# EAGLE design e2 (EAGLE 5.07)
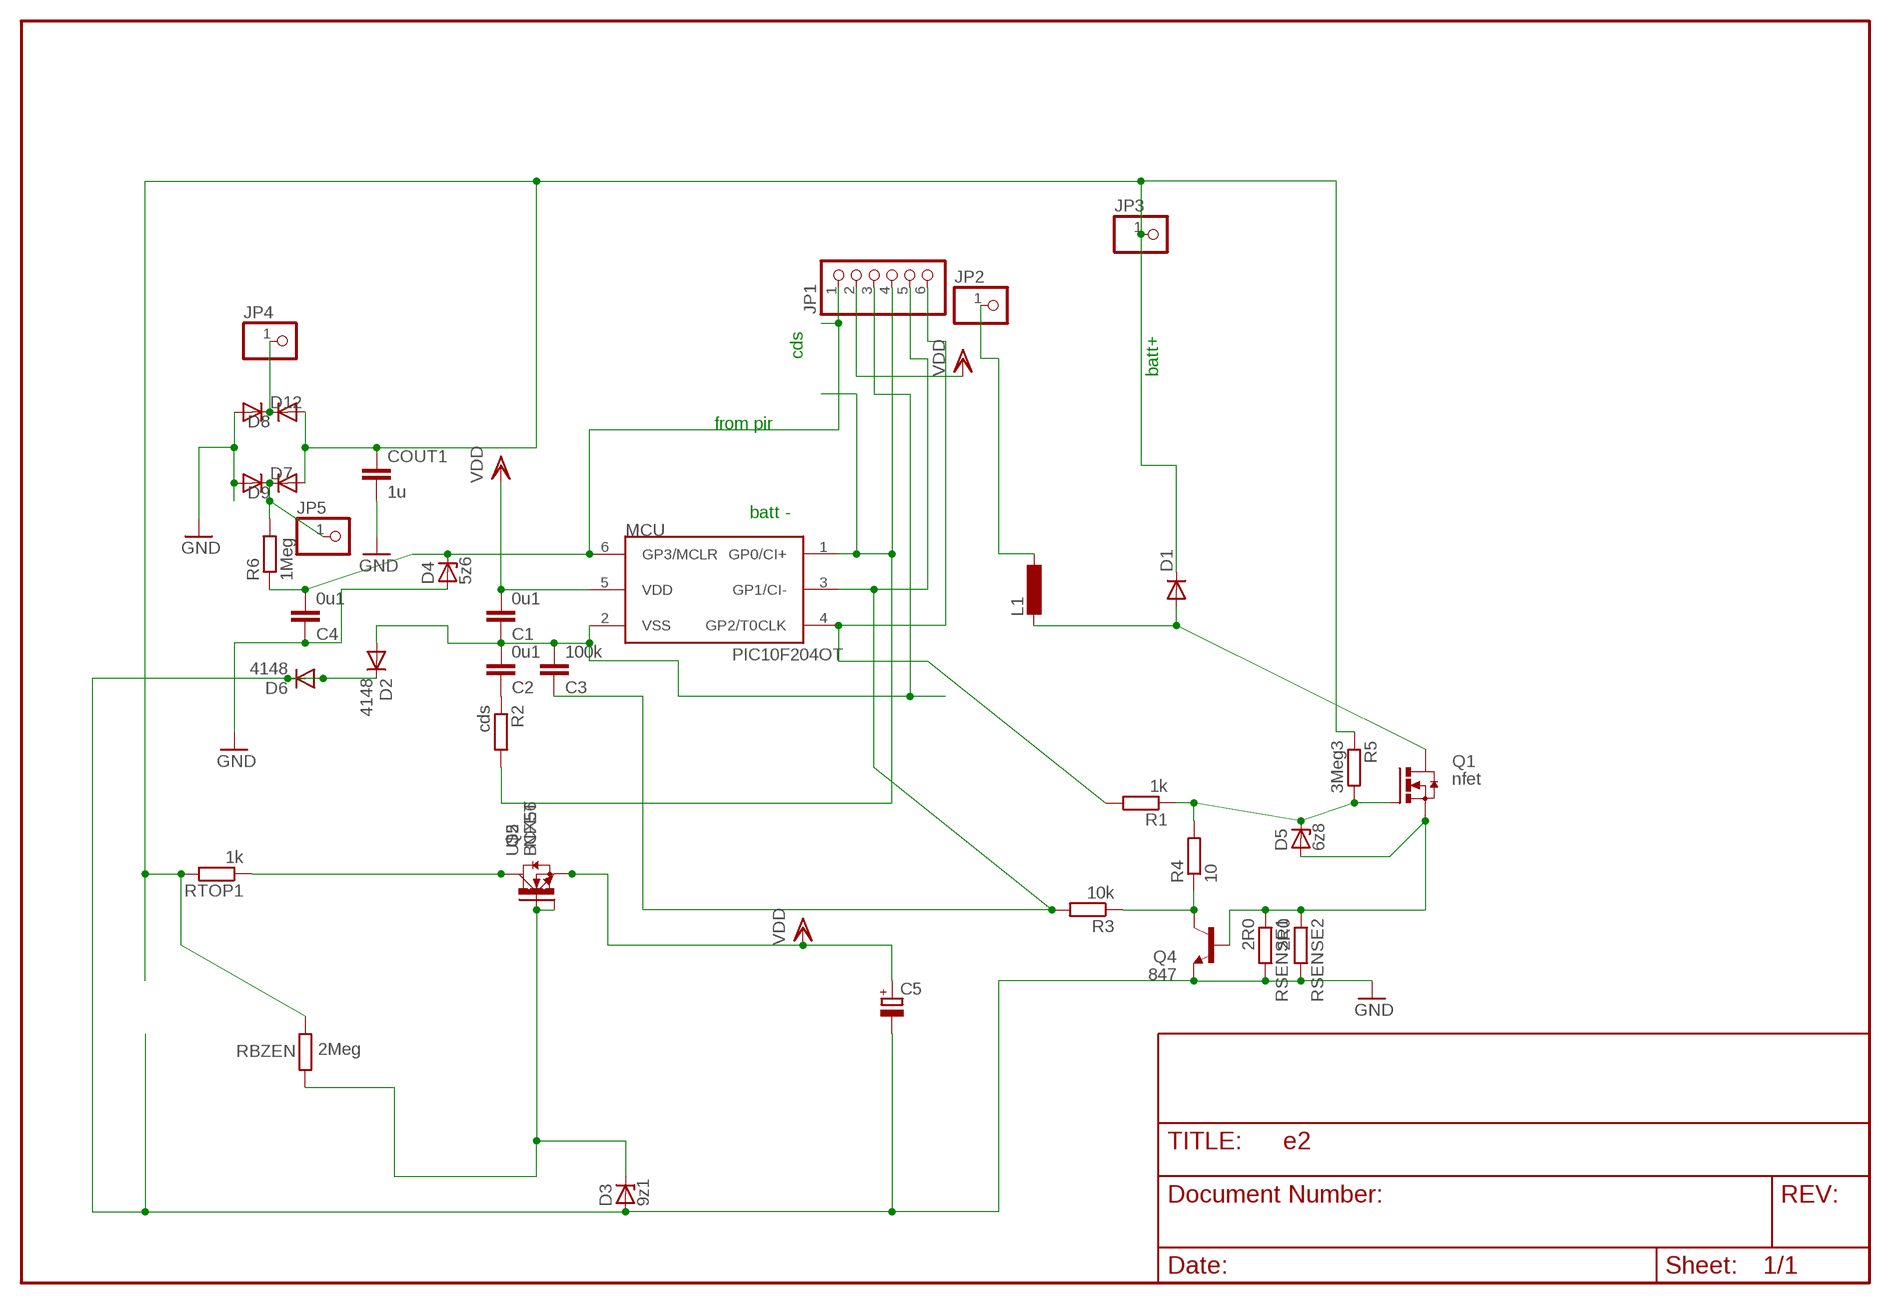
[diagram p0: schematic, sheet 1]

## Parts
C1  0u1  C-EUC1206  [C1206]
C2  0u1  C-EUC0805  [C0805]
C3  100k  C-EUC1206  [C1206]
C4  0u1  C-EUC1206  [C1206]
C5  CPOL-EUSANYO_SMD_C6  [SANYO-OSCON_SMD_C6]
COUT1  1u  C-EU075-032X103  [C075-032X103]
D1  DIODE-SMC  [SMC]
D2  4148  1N4148MINIMELF  [MINIMELF]
D3  9z1  ZENER-DIODESOD80C  [SOD80C]
D4  5z6  ZENER-DIODESOD80C  [SOD80C]
D5  6z8  ZENER-DIODESOD80C  [SOD80C]
D6  4148  1N4148MINIMELF  [MINIMELF]
D7  DIODE-DO214AA  [DO214AA]
D8  DIODE-DO214AA  [DO214AA]
D9  DIODE-DO214AA  [DO214AA]
D12  DIODE-DO214AA  [DO214AA]
JP1  PINHD-1X6  [1X06BOX]
JP2  PINHD-1X11X0.4  [1X01]
JP3  PINHD-1X11MM6  [1X1MM8]
JP4  PINHD-1X11MM6  [1X1MM8]
JP5  PINHD-1X11MM6  [1X1MM8]
L1  L-EUPIS2816  [PIS2816]
MCU  PIC10F204OT  [SOT23-6]
Q1  nfet  N-HEXFET_DPAK-  [TO252]
Q4  847  BC847ASMD  [SOT23]
Q5  NFET  N-HEXFET_DPAK-  [TO252]
R1  1k  R-EU_R0805  [R0805]
R2  cds  R-EU_0204/2V  [0204V]
R3  10k  R-EU_R1206  [R1206]
R4  10  R-EU_R1206  [R1206]
R5  3Meg3  R-EU_R2010  [R2010]
R6  1Meg  R-EU_R2010  [R2010]
RBZEN  2Meg  R-EU_R2010  [R2010]
RSENSE1  2R0  R-EU_R1210  [R1210]
RSENSE2  2R0  R-EU_R2512  [R2512]
RTOP1  1k  R-EU_R1206  [R1206]
U$2  BCX56  [SOT223]

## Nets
AC1: D8.C D12.C JP4.1
AC2: D7.C D9.C JP5.1 R6.2
C: Q5.3(D) RTOP1.1 U$2.2(C)
CB: D3.C Q5.1(G) RBZEN.2 U$2.1(B)
GND: C4.1 C5.- COUT1.2 D2.C D3.A D4.A D6.A D6.C D7.A D12.A Q4.2(E) RSENSE1.2 RSENSE2.2
HOT: D1.A L1.2 Q1.3(D)
LED-: JP2.1 L1.1
N$1: Q4.3(C) R3.1 R4.1
N$2: JP1.4 MCU.1(GP0/CI+) R2.2
N$3: C4.2 D4.C JP1.1 MCU.6(GP3/MCLR) R6.1
N$5: C3.1 JP1.5 MCU.3(GP1/CI-) R3.2
N$7: D5.C Q1.1(G) R1.1 R4.2 R5.2
N$8: C2.1 R2.1
N$14: JP1.6 MCU.4(GP2/T0CLK) R1.2
N$17: D5.A Q1.2(S) Q4.1(B) RSENSE1.1 RSENSE2.1
VDD: C1.2 C5.+ JP1.2 MCU.5(VDD) Q5.2(S) U$2.3(E)
VPLUS: COUT1.1 D1.C D8.A D9.A JP3.1 R5.1 RBZEN.1 RTOP1.2
VSS: C1.1 C2.2 C3.2 D2.A JP1.3 MCU.2(VSS)

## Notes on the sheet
- cds
- batt+
- from pir
- batt -

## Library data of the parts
C1-C4 COUT1 = rcl:C-EU: CAPACITOR, European symbol
C5 = rcl-2:CPOL-EU: POLARIZED CAPACITOR, European symbol
D1 = diode-1:DIODE-: DIODE
D2 D6 = diode-1:1N4148: DIODE
D3-D5 = diode:ZENER-DIODE: Z-Diode
D7-D9 D12 = diode:DIODE-: DIODE
JP1 = pinhead:PINHD-1X6: PIN HEADER
JP2-JP5 = pinhead:PINHD-1X1: PIN HEADER
L1 = rcl:L-EU: INDUCTOR, European symbol
MCU = microchip-3:PIC10F2*: uPC nW 0,25/0,5k Program Flash memory Comparator
Q1 Q5 = transistor-power:N-HEXFET_?-*: HEXFET® Power MOSFET
Q4 = transistor-npn:BC847*: NPN Transistor
R1-R5 RBZEN RSENSE1 RSENSE2 RTOP1 = rcl:R-EU_: RESISTOR, European symbol
R6 = rcl-2:R-EU_: RESISTOR, European symbol
U$2 = transistor-power:BCX56

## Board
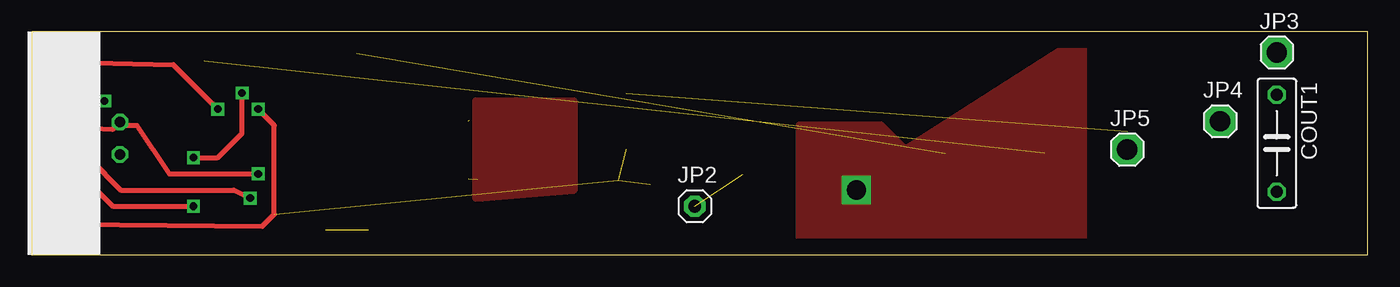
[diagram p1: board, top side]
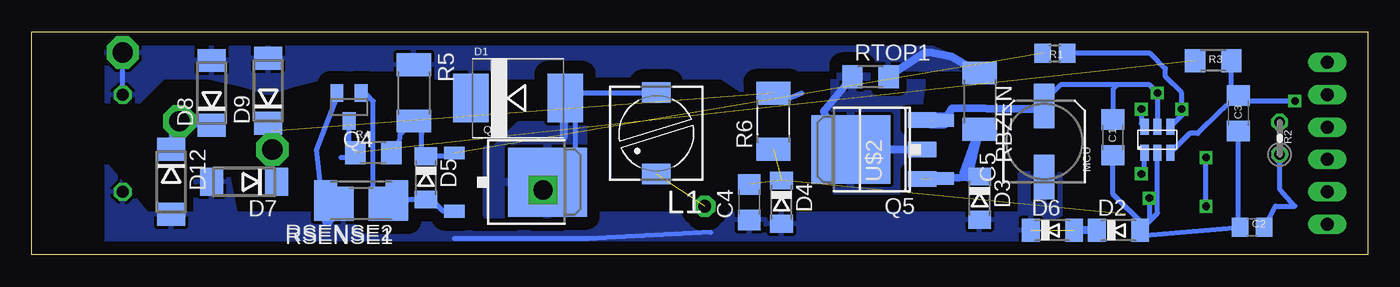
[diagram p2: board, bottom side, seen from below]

Size 104.93 x 17.5 mm. Coordinates in mm from the lower left corner, seen from the top.
Outline: 0,0 104.93,0 104.93,17.5 0,17.5 0,0
Copper layers (1*16): Top 0.035mm / dielectric 1.5mm / Bottom 0.035mm
Design rules "default *": minimum track width 10mil, minimum drill 24mil, track to track 8mil, track to pad 8mil, pad to pad 8mil, via to via 8mil, smd to smd 8mil, copper to edge 20mil, drill to drill 8mil, minimum pad ring 10mil, minimum via ring 8mil, stop-mask expansion 4mil, vias tented up to drill 0mil, thermal gap 10mil

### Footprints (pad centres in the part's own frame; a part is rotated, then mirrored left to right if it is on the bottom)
C1206 = smd 1.6 x 1.8: 1 -1.4,0; 2 1.4,0
C0805 = smd 1.3 x 1.5: 1 -0.95,0; 2 0.95,0
SANYO-OSCON_SMD_C6 = smd 3.5 x 1.6: + 2.8,0; - -2.8,0
C075-032X103 = drill 0.914 octagon: 1 -3.81,0; 2 3.81,0
SMC = smd 2.8 x 3.8: A 3.7,0; C -3.7,0
MINIMELF = smd 1.4 x 1.8: A 1.7,0; C -1.7,0
SOD80C = smd 1.4 x 1.8: A 1.7,0; C -1.7,0
DO214AA = smd 1.8 x 2.2: A 2.55,0; C -2.55,0
1X06BOX = drill 1.016 long: 1 -6.35,0; 2 -3.81,0; 3 -1.27,0; 4 1.27,0; 5 3.81,0; 6 6.35,0
1X01 = drill 1 pad 1.676 octagon: 1 0,0
1X1MM8 = drill 1.6 pad 2.54 octagon: 1 0,0
PIS2816 = smd 2.2 x 1.6: 1 0,3.2; 2 0,-3.2
SOT23-6 = smd 0.635 x 1.27: 1 -1.016,-1.016; 2 0,-1.016; 3 1.016,-1.016; 4 1.016,1.016; 5 0,1.016; 6 -1.016,1.016
TO252 = smd 1 x 1.6: 1 -2.28,-3.53; 2 2.28,-3.53 | smd 5.4 x 6.2: 3 0,3.77
SOT23 = smd 1 x 1.4: 1 -0.95,-1.1; 2 0.95,-1.1; 3 0,1.1
R0805 = smd 1.3 x 1.5: 1 -0.95,0; 2 0.95,0
0204V = drill 0.813 octagon: 1 -1.27,0; 2 1.27,0
R1206 = smd 1.6 x 1.803: 1 -1.422,0; 2 1.422,0
R2010 = smd 1.8 x 2.7: 1 -2.2,0; 2 2.2,0
R1210 = smd 1.6 x 2.7: 1 -1.4,0; 2 1.4,0
R2512 = smd 1.8 x 3.2: 1 -2.8,0; 2 2.8,0
SOT223 = smd 1.219 x 2.235: 1 -2.311,-3.099; 2 0,-3.099; 3 2.311,-3.099 | smd 3.6 x 2.2: 4 0,3.099

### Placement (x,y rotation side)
C1  20,9.21 90 bottom
C2  9.08,2.16 180 bottom
C3  10.16,11.11 270 bottom
C4  48.58,4.13 90 bottom
C5  25.4,8.89 90 bottom
COUT1  97.79,8.75 270 top
D1  66.74,12.3 0 bottom
D2  19.57,1.91 0 bottom
D3  30.48,4.45 270 bottom
D4  46.04,4.13 270 bottom
D5  73.98,6.03 270 bottom
D6  24.77,1.91 0 bottom
D7  88.27,5.71 180 bottom
D8  90.81,12.7 90 bottom
D9  86.36,12.88 90 bottom
D12  93.98,5.71 270 bottom
JP1  3.17,8.75 90 top
JP2  52.07,3.81 0 top
JP3  97.79,15.88 0 top
JP4  93.34,10.48 0 top
JP5  86.04,8.26 0 top
L1  55.88,9.53 180 bottom
MCU  16.51,9.03 0 bottom
Q1  68.2,5.7 270 bottom
Q4  80.01,11.6 180 bottom
Q5  36.83,8.26 90 bottom
R1  24.57,15.81 0 bottom
R2  6.92,9.14 90 bottom
R3  12.13,15.24 0 bottom
R4  78.11,8 0 bottom
R5  74.93,12.7 270 bottom
R6  46.67,10.48 90 bottom
RBZEN  30.48,12.06 270 bottom
RSENSE1  79.06,4 180 bottom
RSENSE2  79.06,4.25 180 bottom
RTOP1  39.05,13.97 0 bottom
U$2  38.1,8.26 90 bottom

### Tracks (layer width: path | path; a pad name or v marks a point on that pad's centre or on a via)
AC1
  Bottom 0.406: D8.C 93.02,10.15 JP4.1 93.97,9.85 D12.C
AC2  (1 unrouted)
  Bottom 0.406: D9.C 86.04,9.7 JP5.1 86.04,5.71 D7.C | 44.45,12.7 46.06,12.06 R6.2
C
  Bottom 0.406: 41.27,10.16 40.64,10.16 40.64,9.53
  Bottom 0.61: 40.01,8.26 40.64,9.53 | U$2.2 39.37,8.26 | 39.37,8.26 40.01,8.26 | RTOP1.1 42.7,11.28 41.91,9.53 39.37,8.26 | 40.01,8.26 Q5.3
  pour Bottom (isolate 0.61, rank 5): 34.92,13.97 41.91,13.97 41.91,5.08 36.2,5.08
  pour Top (isolate 0.61, rank 4): 34.92,12.06 42.55,12.06 42.55,5.08 34.92,4.45
CB  (1 unrouted)
  Bottom 0.61: D3.C 31.75,6.35 RBZEN.2 31.39,6.07 Q5.1 34.29,5.97
GND  (1 unrouted)
  Bottom 0.406: 71.75,1.27 61.28,1.27 51.58,1.76 | Q4.2 80.96,12.38 82.55,8.26 81.92,2.54 81.46,2.54 RSENSE1.2 81.57,3.57 RSENSE2.2
  Bottom 0.61: D2.C D6.A
  pour Bottom (isolate 1.016, rank 4): 89.53,6.35 92.08,6.35 92.08,3.17 95.89,3.17 99.06,6.99 99.06,0.64 25.72,0.64 25.72,2.54 24.13,3.17 24.13,6.35 27.3,6.35 27.3,3.17 88.9,3.17
HOT  (via drill 1.5)
  Bottom 0.406: Q1.3 64.43,6.35 62.23,6.35 62.23,11.43 62.23,12.13 D1.A 63.04,12.72 L1.2
  Bottom 0.61: 63.18,9.21 63.18,11.11 62.87,11.43 62.23,11.43
  other vias: 64.77,5.08
  pour Bottom: 61.59,10.16 66.67,10.16 68.58,8.26 69.22,8.26 69.22,3.17 61.59,3.17
  pour Top (isolate 1.27): 60.33,10.16 66.67,10.16 68.58,8.26 82.55,17.14 82.55,1.27 60.33,1.27
LED-  (1 unrouted)
N$1  (1 unrouted)
  Bottom 0.406: Q4.3 80.01,8.3 R4.1 79.73,7.62 80.64,7.62
N$2  (via drill 0.6)
  Top 0.406: JP1.4 6.35,9.84 R2.2 7.18,10.16 8.26,10.16 10.79,6.35 v17.78,6.35
  Bottom 0.406: MCU.1 17.53,6.6 v17.78,6.35
N$3  (via drill 0.6)  (3 unrouted)
  Top 0.406: JP1.1 18.1,2.22 19.05,3.17 19.05,10.16 v17.78,11.43
  Bottom 0.406: v17.78,11.43 17.78,10.3 MCU.6
N$5  (via drill 0.6)
  Top 0.406: JP1.5 5.4,12.38 v5.71,12.06
  Bottom 0.406: v5.71,12.06 10.61,12.06 | 10.61,12.06 10.71,11.97 R3.2 | 10.61,12.06 C3.1 11.62,11.24 13.34,9.53 13.98,9.53 MCU.3
N$7  (1 unrouted)
  Bottom 0.406: R5.2 74.45,10 74.3,9.53 74.3,8.05 D5.C 71.99,7.73 Q1.1 | R4.2 76.03,9.11 76.03,9.4 R5.2 | R5.2 74.93,10.59
N$8
  Bottom 0.406: R2.1 6.92,5.14 5.71,3.81 7.24,3.81 C2.1
N$14  (via drill 0.6)
  Top 0.406: JP1.6 11.11,14.92 v14.61,11.43
  Bottom 0.406: MCU.4 14.61,10.94 v14.61,11.43 14.61,12.7 15.88,13.97 15.88,14.61 17.08,15.81 R1.2
N$17
  Bottom 0.406: Q4.1 78.57,12.53 78.11,12.06 78.11,4.48 RSENSE1.1 | Q1.2 72.65,3.44 73.66,4.45 73.86,4.45 D5.A 75.52,4.33 75.55,4.3 76.29,4.3 RSENSE2.1
  Bottom 0.61: 75.55,4.3 RSENSE1.1
VDD  (via drill 0.6)  (1 unrouted)
  Top 0.406: JP1.2 5.22,4.94 6.35,3.81 v12.7,3.81 | v12.7,7.62 14.61,7.62 16.51,9.53 v16.51,12.7
  Bottom 0.406: U$2.3 34.34,10.54 | v12.7,3.81 v12.7,7.62 | MCU.5 v16.51,12.7 17.14,13.34 19.68,13.34 | C5.+ 25.4,12.06 24.13,13.34 19.68,13.34 | C1.2 20,13.02 19.68,13.34
  Bottom 0.61: Q5.2 32.65,11.49 27.3,11.43 26.04,11.43 C5.+
  Bottom 1.27: Q5.2 34.28,10.54
VPLUS
  Bottom 0.406: COUT1.1 JP3.1
  Bottom 0.61: RBZEN.1 32.7,15.56 34.29,15.88 34.77,15.88 RTOP1.2
  pour Bottom (isolate 1.016, rank 3): 99.06,12.06 96.52,12.06 94.61,13.97 91.12,13.97 88.27,13.34 86.36,12.7 84.45,13.34 81.92,13.97 81.28,14.61 74.3,14.61 73.66,13.97 50.8,13.97 48.9,12.7 48.26,12.7 46.35,14.61 30.48,14.61 34.92,16.51 99.06,16.51
VSS  (via drill 0.6)
  Top 0.406: JP1.3 4.58,7.48 6.99,5.08 15.88,5.08 v17.14,4.45
  Bottom 0.406: MCU.2 16.51,3.27 17.51,2.27 | D2.A 17.51,2.27 | C1.1 20,4.76 17.51,2.27 | D2.A 17.49,1.52 C2.2 10.16,2.29 C3.2 | v17.14,4.45 17.14,2.63 D2.A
